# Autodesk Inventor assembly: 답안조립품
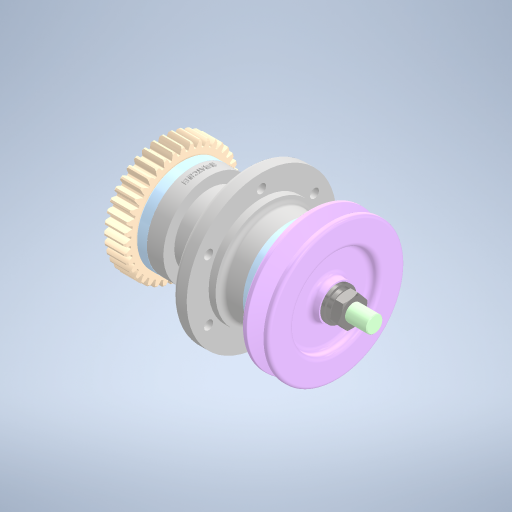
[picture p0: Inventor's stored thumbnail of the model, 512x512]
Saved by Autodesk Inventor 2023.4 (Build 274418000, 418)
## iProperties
Created: 2024-04
Part Number: 답안조립품
Document SubType Name: Assembly
Designer: Edu03
Author: Edu03
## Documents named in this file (18)
- C:\Users\Edu03\Desktop\740404V1004\답안조립품.iam
- C:\Users\Edu03\Desktop\740404V1004\V-벨트풀리\V-벨트풀리.ipt
- C:\Users\Edu03\Desktop\740404V1004\깊은 홈 볼 베어링 6204\깊은 홈 볼 베어링 6204.ipt
- C:\Users\Edu03\Desktop\740404V1004\스프링와셔 M12\스프링와셔 M12.ipt
- C:\Users\Edu03\Desktop\740404V1004\오일 실 20 32 5\오일 실 20 32 5.ipt
- C:\Users\Edu03\Desktop\740404V1004\육각 소켓 머리 볼트 M4x10\육각 소켓 머리 볼트 M4x10.ipt
- C:\Users\Edu03\Desktop\740404V1004\육각너트 M12x1\육각너트 M12x1.ipt
- C:\Users\Edu03\Desktop\740404V1004\축\축.ipt
- C:\Users\Edu03\Desktop\740404V1004\커버\커버.ipt
- C:\Users\Edu03\Desktop\740404V1004\평와셔 M12\평와셔 M12.ipt
- C:\Users\Edu03\Desktop\740404V1004\평행키 4x4x12\평행키 4x4x12.ipt
- C:\Users\Edu03\Desktop\740404V1004\평행키 4x4x18\평행키 4x4x18.ipt
- C:\Users\Edu03\Desktop\740404V1004\본체.ipt
- C:\Users\Edu03\Desktop\740404V1004\스퍼기어.ipt
- C:\Users\Edu03\Desktop\740404V1004\오일 실 20 32 5.ipt
- C:\Users\Edu03\Desktop\740404V1004\평와셔 M12.ipt
- C:\Users\Edu03\Desktop\740404V1004\스프링와셔 M12.ipt
- C:\Users\Edu03\Desktop\740404V1004\육각너트 M12x1.ipt
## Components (1 placed, 1 different names)
1. V-벨트풀리:1
